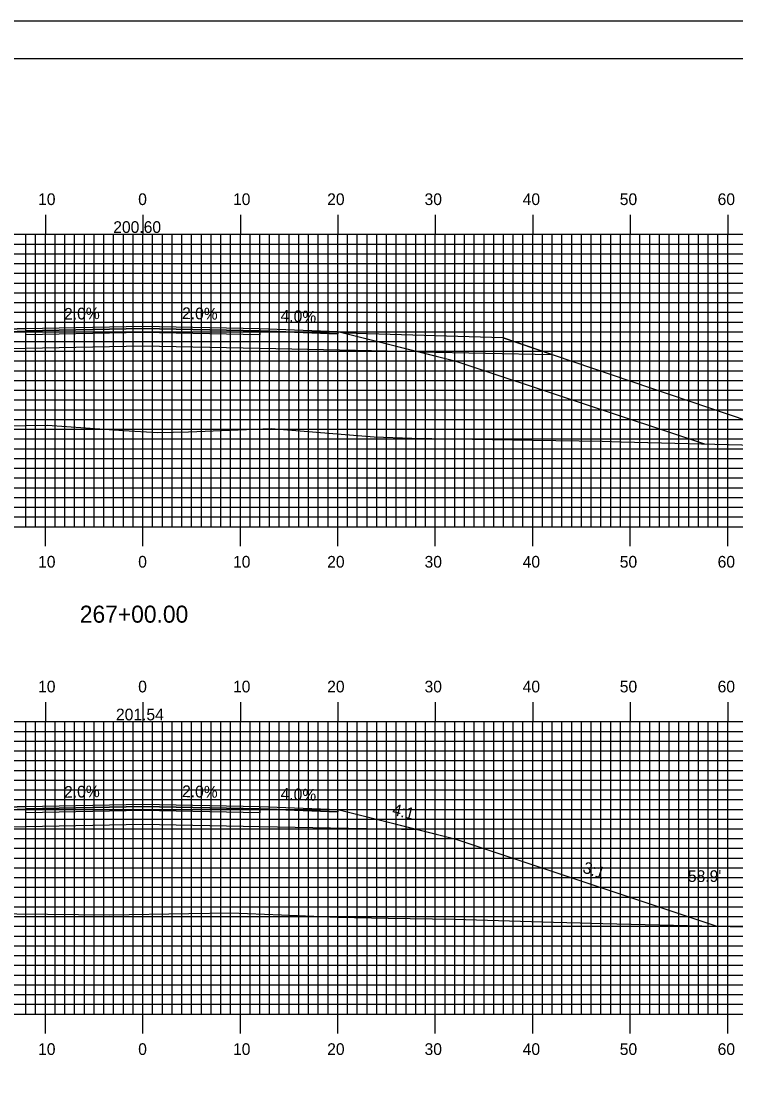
# Model space of a CAD drawing. Extents: x 1807438 to 1807782, y 442591 to 442811.
# Drawn here: x 1807591.8 to 1807665.1, y 442702.5 to 442810.5 of the extents above; entities that cross this region are included whole.
import ezdxf

# ---------------------------------------------------------------- set-up
doc = ezdxf.new("R2010")
doc.units = 0
for name, color, linetype in [('ANNOTATION', 7, 'Continuous'), ('BORDER', 7, 'Continuous'), ('D_Roadway_Centerline', 7, 'Continuous'), ('D_Roadway_Centerline_Text', 7, 'Continuous'), ('D_Roadway_Edge_Shoulder', 7, 'Continuous'), ('D_Roadway_Edge_TW', 7, 'Continuous'), ('D_Roadway_Pavement', 7, 'Continuous'), ('D_Roadway_SlopeLines', 7, 'Continuous'), ('D_Roadway_SubGrade', 7, 'Continuous'), ('D_Text_Standard', 7, 'Continuous'), ('H_V ANNOTATION', 7, 'Continuous'), ('MAJOR', 7, 'Continuous'), ('MINOR', 7, 'Continuous'), ('PLOT BOUNDARY', 7, 'Continuous'), ('S_Roadway_Centerline', 7, 'Continuous')]:
    doc.layers.add(name, color=color, linetype=linetype)

msp = doc.modelspace()

# ---------------------------------------------------------------- linework, layer by layer
at = {"layer": 'BORDER'}
msp.add_lwpolyline([(1807454.67, 442596.67), (1807774.67, 442596.67), (1807774.67, 442806.67), (1807454.67, 442806.67)], close=True, dxfattribs=at)
at = {"layer": 'D_Roadway_Centerline'}
for points in [[(1807554.39, 442769.74), (1807572.27, 442775.7), (1807575.91, 442776.61), (1807584.27, 442778.7), (1807592.27, 442779.02), (1807604.27, 442779.26), (1807616.27, 442779.02), (1807624.27, 442778.7), (1807632.63, 442776.61), (1807636.27, 442775.7), (1807661.88, 442767.17)], [(1807552.34, 442720), (1807572.27, 442726.65), (1807575.91, 442727.56), (1807584.27, 442729.65), (1807592.27, 442729.97), (1807604.27, 442730.21), (1807616.27, 442729.97), (1807624.27, 442729.65), (1807632.63, 442727.56), (1807636.27, 442726.65), (1807663.15, 442717.69)]]:
    msp.add_lwpolyline(points, dxfattribs=at)
at = {"layer": 'D_Roadway_Edge_Shoulder'}
for points in [[(1807592.27, 442779.02), (1807584.27, 442778.7), (1807584.27, 442778.45), (1807592.27, 442778.77)], [(1807616.27, 442779.02), (1807624.27, 442778.7), (1807624.27, 442778.45), (1807616.27, 442778.77)], [(1807592.27, 442729.97), (1807584.27, 442729.65), (1807584.27, 442729.4), (1807592.27, 442729.72)], [(1807616.27, 442729.97), (1807624.27, 442729.65), (1807624.27, 442729.4), (1807616.27, 442729.72)]]:
    msp.add_lwpolyline(points, close=True, dxfattribs=at)
at = {"layer": 'D_Roadway_Edge_TW'}
for points in [[(1807592.27, 442778.77), (1807592.27, 442779.02), (1807604.27, 442779.26), (1807616.27, 442779.02), (1807616.27, 442778.77), (1807604.27, 442779.01)], [(1807592.27, 442729.72), (1807592.27, 442729.97), (1807604.27, 442730.21), (1807616.27, 442729.97), (1807616.27, 442729.72), (1807604.27, 442729.96)]]:
    msp.add_lwpolyline(points, close=True, dxfattribs=at)
at = {"layer": 'D_Roadway_Pavement'}
for points in [[(1807592.27, 442778.36), (1807592.27, 442778.77), (1807604.27, 442779.01), (1807616.27, 442778.77), (1807616.27, 442778.36), (1807604.27, 442778.6)], [(1807592.27, 442729.3), (1807592.27, 442729.72), (1807604.27, 442729.96), (1807616.27, 442729.72), (1807616.27, 442729.3), (1807604.27, 442729.54)]]:
    msp.add_lwpolyline(points, close=True, dxfattribs=at)
at = {"layer": 'D_Roadway_SlopeLines'}
for points in [[(1807624.27, 442778.7), (1807636.27, 442775.7), (1807661.88, 442767.17)], [(1807632.63, 442776.61), (1807646.24, 442776.34), (1807641.22, 442778.04), (1807624.98, 442778.52)], [(1807641.22, 442778.04), (1807644.46, 442776.94), (1807674.31, 442766.84)], [(1807624.27, 442729.65), (1807636.27, 442726.65), (1807663.15, 442717.69)]]:
    msp.add_lwpolyline(points, dxfattribs=at)
at = {"layer": 'D_Roadway_SubGrade'}
for points in [[(1807592.27, 442776.94), (1807575.91, 442776.61), (1807584.27, 442778.7), (1807584.27, 442778.45), (1807592.27, 442778.77), (1807604.27, 442779.01), (1807616.27, 442778.77), (1807624.27, 442778.45), (1807624.27, 442778.7), (1807632.63, 442776.61), (1807616.27, 442776.94), (1807604.27, 442777.18)], [(1807592.27, 442727.88), (1807575.91, 442727.56), (1807584.27, 442729.65), (1807584.27, 442729.4), (1807592.27, 442729.72), (1807604.27, 442729.96), (1807616.27, 442729.72), (1807624.27, 442729.4), (1807624.27, 442729.65), (1807632.63, 442727.56), (1807616.27, 442727.88), (1807604.27, 442728.12)]]:
    msp.add_lwpolyline(points, close=True, dxfattribs=at)
at = {"layer": 'MAJOR'}
for p, q in [((1807594.27, 442790.67), (1807594.27, 442788.67)), ((1807604.27, 442790.67), (1807604.27, 442788.67)), ((1807614.27, 442790.67), (1807614.27, 442788.67)), ((1807624.27, 442790.67), (1807624.27, 442788.67)), ((1807634.27, 442790.67), (1807634.27, 442788.67)), ((1807644.27, 442790.67), (1807644.27, 442788.67)), ((1807654.27, 442790.67), (1807654.27, 442788.67)), ((1807664.27, 442790.67), (1807664.27, 442788.67)), ((1807464.27, 442788.67), (1807744.27, 442788.67)), ((1807464.27, 442788.67), (1807744.27, 442788.67)), ((1807594.27, 442758.67), (1807594.27, 442788.67)), ((1807604.27, 442758.67), (1807604.27, 442788.67)), ((1807614.27, 442758.67), (1807614.27, 442788.67)), ((1807624.27, 442758.67), (1807624.27, 442788.67)), ((1807634.27, 442758.67), (1807634.27, 442788.67)), ((1807644.27, 442758.67), (1807644.27, 442788.67)), ((1807654.27, 442758.67), (1807654.27, 442788.67)), ((1807664.27, 442758.67), (1807664.27, 442788.67)), ((1807464.27, 442783.67), (1807744.27, 442783.67)), ((1807464.27, 442778.67), (1807744.27, 442778.67)), ((1807464.27, 442773.67), (1807744.27, 442773.67)), ((1807464.27, 442768.67), (1807744.27, 442768.67)), ((1807464.27, 442763.67), (1807744.27, 442763.67)), ((1807464.27, 442758.67), (1807744.27, 442758.67)), ((1807464.27, 442758.67), (1807744.27, 442758.67)), ((1807594.27, 442756.66), (1807594.27, 442758.67)), ((1807604.27, 442756.66), (1807604.27, 442758.67)), ((1807614.27, 442756.66), (1807614.27, 442758.67)), ((1807624.27, 442756.66), (1807624.27, 442758.67)), ((1807634.27, 442756.66), (1807634.27, 442758.67)), ((1807644.27, 442756.66), (1807644.27, 442758.67)), ((1807654.27, 442756.66), (1807654.27, 442758.67)), ((1807664.27, 442756.66), (1807664.27, 442758.67)), ((1807594.27, 442740.67), (1807594.27, 442738.67)), ((1807604.27, 442740.67), (1807604.27, 442738.67)), ((1807614.27, 442740.67), (1807614.27, 442738.67)), ((1807624.27, 442740.67), (1807624.27, 442738.67)), ((1807634.27, 442740.67), (1807634.27, 442738.67)), ((1807644.27, 442740.67), (1807644.27, 442738.67)), ((1807654.27, 442740.67), (1807654.27, 442738.67)), ((1807664.27, 442740.67), (1807664.27, 442738.67)), ((1807464.27, 442738.67), (1807744.27, 442738.67)), ((1807464.27, 442738.67), (1807744.27, 442738.67)), ((1807594.27, 442708.67), (1807594.27, 442738.67)), ((1807604.27, 442708.67), (1807604.27, 442738.67)), ((1807614.27, 442708.67), (1807614.27, 442738.67)), ((1807624.27, 442708.67), (1807624.27, 442738.67)), ((1807634.27, 442708.67), (1807634.27, 442738.67)), ((1807644.27, 442708.67), (1807644.27, 442738.67)), ((1807654.27, 442708.67), (1807654.27, 442738.67)), ((1807664.27, 442708.67), (1807664.27, 442738.67)), ((1807464.27, 442733.67), (1807744.27, 442733.67)), ((1807464.27, 442728.67), (1807744.27, 442728.67)), ((1807464.27, 442723.67), (1807744.27, 442723.67)), ((1807464.27, 442718.67), (1807744.27, 442718.67)), ((1807464.27, 442713.67), (1807744.27, 442713.67)), ((1807464.27, 442708.67), (1807744.27, 442708.67)), ((1807464.27, 442708.67), (1807744.27, 442708.67)), ((1807594.27, 442706.66), (1807594.27, 442708.67)), ((1807604.27, 442706.66), (1807604.27, 442708.67)), ((1807614.27, 442706.66), (1807614.27, 442708.67)), ((1807624.27, 442706.66), (1807624.27, 442708.67)), ((1807634.27, 442706.66), (1807634.27, 442708.67)), ((1807644.27, 442706.66), (1807644.27, 442708.67)), ((1807654.27, 442706.66), (1807654.27, 442708.67)), ((1807664.27, 442706.66), (1807664.27, 442708.67))]:
    msp.add_line(p, q, dxfattribs=at)
at = {"layer": 'MINOR'}
for p, q in [((1807592.27, 442758.67), (1807592.27, 442788.67)), ((1807593.27, 442758.67), (1807593.27, 442788.67)), ((1807595.27, 442758.67), (1807595.27, 442788.67)), ((1807596.27, 442758.67), (1807596.27, 442788.67)), ((1807597.27, 442758.67), (1807597.27, 442788.67)), ((1807598.27, 442758.67), (1807598.27, 442788.67)), ((1807599.27, 442758.67), (1807599.27, 442788.67)), ((1807600.27, 442758.67), (1807600.27, 442788.67)), ((1807601.27, 442758.67), (1807601.27, 442788.67)), ((1807602.27, 442758.67), (1807602.27, 442788.67)), ((1807603.27, 442758.67), (1807603.27, 442788.67)), ((1807605.27, 442758.67), (1807605.27, 442788.67)), ((1807606.27, 442758.67), (1807606.27, 442788.67)), ((1807607.27, 442758.67), (1807607.27, 442788.67)), ((1807608.27, 442758.67), (1807608.27, 442788.67)), ((1807609.27, 442758.67), (1807609.27, 442788.67)), ((1807610.27, 442758.67), (1807610.27, 442788.67)), ((1807611.27, 442758.67), (1807611.27, 442788.67)), ((1807612.27, 442758.67), (1807612.27, 442788.67)), ((1807613.27, 442758.67), (1807613.27, 442788.67)), ((1807615.27, 442758.67), (1807615.27, 442788.67)), ((1807616.27, 442758.67), (1807616.27, 442788.67)), ((1807617.27, 442758.67), (1807617.27, 442788.67)), ((1807618.27, 442758.67), (1807618.27, 442788.67)), ((1807619.27, 442758.67), (1807619.27, 442788.67)), ((1807620.27, 442758.67), (1807620.27, 442788.67)), ((1807621.27, 442758.67), (1807621.27, 442788.67)), ((1807622.27, 442758.67), (1807622.27, 442788.67)), ((1807623.27, 442758.67), (1807623.27, 442788.67)), ((1807625.27, 442758.67), (1807625.27, 442788.67)), ((1807626.27, 442758.67), (1807626.27, 442788.67)), ((1807627.27, 442758.67), (1807627.27, 442788.67)), ((1807628.27, 442758.67), (1807628.27, 442788.67)), ((1807629.27, 442758.67), (1807629.27, 442788.67)), ((1807630.27, 442758.67), (1807630.27, 442788.67)), ((1807631.27, 442758.67), (1807631.27, 442788.67)), ((1807632.27, 442758.67), (1807632.27, 442788.67)), ((1807633.27, 442758.67), (1807633.27, 442788.67)), ((1807635.27, 442758.67), (1807635.27, 442788.67)), ((1807636.27, 442758.67), (1807636.27, 442788.67)), ((1807637.27, 442758.67), (1807637.27, 442788.67)), ((1807638.27, 442758.67), (1807638.27, 442788.67)), ((1807639.27, 442758.67), (1807639.27, 442788.67)), ((1807640.27, 442758.67), (1807640.27, 442788.67)), ((1807641.27, 442758.67), (1807641.27, 442788.67)), ((1807642.27, 442758.67), (1807642.27, 442788.67)), ((1807643.27, 442758.67), (1807643.27, 442788.67)), ((1807645.27, 442758.67), (1807645.27, 442788.67)), ((1807646.27, 442758.67), (1807646.27, 442788.67)), ((1807647.27, 442758.67), (1807647.27, 442788.67)), ((1807648.27, 442758.67), (1807648.27, 442788.67)), ((1807649.27, 442758.67), (1807649.27, 442788.67)), ((1807650.27, 442758.67), (1807650.27, 442788.67)), ((1807651.27, 442758.67), (1807651.27, 442788.67)), ((1807652.27, 442758.67), (1807652.27, 442788.67)), ((1807653.27, 442758.67), (1807653.27, 442788.67)), ((1807655.27, 442758.67), (1807655.27, 442788.67)), ((1807656.27, 442758.67), (1807656.27, 442788.67)), ((1807657.27, 442758.67), (1807657.27, 442788.67)), ((1807658.27, 442758.67), (1807658.27, 442788.67)), ((1807659.27, 442758.67), (1807659.27, 442788.67)), ((1807660.27, 442758.67), (1807660.27, 442788.67)), ((1807661.27, 442758.67), (1807661.27, 442788.67)), ((1807662.27, 442758.67), (1807662.27, 442788.67)), ((1807663.27, 442758.67), (1807663.27, 442788.67)), ((1807464.27, 442787.67), (1807744.27, 442787.67)), ((1807464.27, 442786.67), (1807744.27, 442786.67)), ((1807464.27, 442785.67), (1807744.27, 442785.67)), ((1807464.27, 442784.67), (1807744.27, 442784.67)), ((1807464.27, 442782.67), (1807744.27, 442782.67)), ((1807464.27, 442781.67), (1807744.27, 442781.67)), ((1807464.27, 442780.67), (1807744.27, 442780.67)), ((1807464.27, 442779.67), (1807744.27, 442779.67)), ((1807464.27, 442777.67), (1807744.27, 442777.67)), ((1807464.27, 442776.67), (1807744.27, 442776.67)), ((1807464.27, 442775.67), (1807744.27, 442775.67)), ((1807464.27, 442774.67), (1807744.27, 442774.67)), ((1807464.27, 442772.67), (1807744.27, 442772.67)), ((1807464.27, 442771.67), (1807744.27, 442771.67)), ((1807464.27, 442770.67), (1807744.27, 442770.67)), ((1807464.27, 442769.67), (1807744.27, 442769.67)), ((1807464.27, 442767.67), (1807744.27, 442767.67)), ((1807464.27, 442766.67), (1807744.27, 442766.67)), ((1807464.27, 442765.67), (1807744.27, 442765.67)), ((1807464.27, 442764.67), (1807744.27, 442764.67)), ((1807464.27, 442762.67), (1807744.27, 442762.67)), ((1807464.27, 442761.67), (1807744.27, 442761.67)), ((1807464.27, 442760.67), (1807744.27, 442760.67)), ((1807464.27, 442759.67), (1807744.27, 442759.67)), ((1807592.27, 442708.67), (1807592.27, 442738.67)), ((1807593.27, 442708.67), (1807593.27, 442738.67)), ((1807595.27, 442708.67), (1807595.27, 442738.67)), ((1807596.27, 442708.67), (1807596.27, 442738.67)), ((1807597.27, 442708.67), (1807597.27, 442738.67)), ((1807598.27, 442708.67), (1807598.27, 442738.67)), ((1807599.27, 442708.67), (1807599.27, 442738.67)), ((1807600.27, 442708.67), (1807600.27, 442738.67)), ((1807601.27, 442708.67), (1807601.27, 442738.67)), ((1807602.27, 442708.67), (1807602.27, 442738.67)), ((1807603.27, 442708.67), (1807603.27, 442738.67)), ((1807605.27, 442708.67), (1807605.27, 442738.67)), ((1807606.27, 442708.67), (1807606.27, 442738.67)), ((1807607.27, 442708.67), (1807607.27, 442738.67)), ((1807608.27, 442708.67), (1807608.27, 442738.67)), ((1807609.27, 442708.67), (1807609.27, 442738.67)), ((1807610.27, 442708.67), (1807610.27, 442738.67)), ((1807611.27, 442708.67), (1807611.27, 442738.67)), ((1807612.27, 442708.67), (1807612.27, 442738.67)), ((1807613.27, 442708.67), (1807613.27, 442738.67)), ((1807615.27, 442708.67), (1807615.27, 442738.67)), ((1807616.27, 442708.67), (1807616.27, 442738.67)), ((1807617.27, 442708.67), (1807617.27, 442738.67)), ((1807618.27, 442708.67), (1807618.27, 442738.67)), ((1807619.27, 442708.67), (1807619.27, 442738.67)), ((1807620.27, 442708.67), (1807620.27, 442738.67)), ((1807621.27, 442708.67), (1807621.27, 442738.67)), ((1807622.27, 442708.67), (1807622.27, 442738.67)), ((1807623.27, 442708.67), (1807623.27, 442738.67)), ((1807625.27, 442708.67), (1807625.27, 442738.67)), ((1807626.27, 442708.67), (1807626.27, 442738.67)), ((1807627.27, 442708.67), (1807627.27, 442738.67)), ((1807628.27, 442708.67), (1807628.27, 442738.67)), ((1807629.27, 442708.67), (1807629.27, 442738.67)), ((1807630.27, 442708.67), (1807630.27, 442738.67)), ((1807631.27, 442708.67), (1807631.27, 442738.67)), ((1807632.27, 442708.67), (1807632.27, 442738.67)), ((1807633.27, 442708.67), (1807633.27, 442738.67)), ((1807635.27, 442708.67), (1807635.27, 442738.67)), ((1807636.27, 442708.67), (1807636.27, 442738.67)), ((1807637.27, 442708.67), (1807637.27, 442738.67)), ((1807638.27, 442708.67), (1807638.27, 442738.67)), ((1807639.27, 442708.67), (1807639.27, 442738.67)), ((1807640.27, 442708.67), (1807640.27, 442738.67)), ((1807641.27, 442708.67), (1807641.27, 442738.67)), ((1807642.27, 442708.67), (1807642.27, 442738.67)), ((1807643.27, 442708.67), (1807643.27, 442738.67)), ((1807645.27, 442708.67), (1807645.27, 442738.67)), ((1807646.27, 442708.67), (1807646.27, 442738.67)), ((1807647.27, 442708.67), (1807647.27, 442738.67)), ((1807648.27, 442708.67), (1807648.27, 442738.67)), ((1807649.27, 442708.67), (1807649.27, 442738.67)), ((1807650.27, 442708.67), (1807650.27, 442738.67)), ((1807651.27, 442708.67), (1807651.27, 442738.67)), ((1807652.27, 442708.67), (1807652.27, 442738.67)), ((1807653.27, 442708.67), (1807653.27, 442738.67)), ((1807655.27, 442708.67), (1807655.27, 442738.67)), ((1807656.27, 442708.67), (1807656.27, 442738.67)), ((1807657.27, 442708.67), (1807657.27, 442738.67)), ((1807658.27, 442708.67), (1807658.27, 442738.67)), ((1807659.27, 442708.67), (1807659.27, 442738.67)), ((1807660.27, 442708.67), (1807660.27, 442738.67)), ((1807661.27, 442708.67), (1807661.27, 442738.67)), ((1807662.27, 442708.67), (1807662.27, 442738.67)), ((1807663.27, 442708.67), (1807663.27, 442738.67)), ((1807464.27, 442737.67), (1807744.27, 442737.67)), ((1807464.27, 442736.67), (1807744.27, 442736.67)), ((1807464.27, 442735.67), (1807744.27, 442735.67)), ((1807464.27, 442734.67), (1807744.27, 442734.67)), ((1807464.27, 442732.67), (1807744.27, 442732.67)), ((1807464.27, 442731.67), (1807744.27, 442731.67)), ((1807464.27, 442730.67), (1807744.27, 442730.67)), ((1807464.27, 442729.67), (1807744.27, 442729.67)), ((1807464.27, 442727.67), (1807744.27, 442727.67)), ((1807464.27, 442726.67), (1807744.27, 442726.67)), ((1807464.27, 442725.67), (1807744.27, 442725.67)), ((1807464.27, 442724.67), (1807744.27, 442724.67)), ((1807464.27, 442722.67), (1807744.27, 442722.67)), ((1807464.27, 442721.67), (1807744.27, 442721.67)), ((1807464.27, 442720.67), (1807744.27, 442720.67)), ((1807464.27, 442719.67), (1807744.27, 442719.67)), ((1807464.27, 442717.67), (1807744.27, 442717.67)), ((1807464.27, 442716.67), (1807744.27, 442716.67)), ((1807464.27, 442715.67), (1807744.27, 442715.67)), ((1807464.27, 442714.67), (1807744.27, 442714.67)), ((1807464.27, 442712.67), (1807744.27, 442712.67)), ((1807464.27, 442711.67), (1807744.27, 442711.67)), ((1807464.27, 442710.67), (1807744.27, 442710.67)), ((1807464.27, 442709.67), (1807744.27, 442709.67))]:
    msp.add_line(p, q, dxfattribs=at)
at = {"layer": 'PLOT BOUNDARY'}
msp.add_lwpolyline([(1807438.49, 442590.55), (1807778.49, 442590.55), (1807778.49, 442810.55), (1807438.49, 442810.55)], close=True, dxfattribs=at)
at = {"layer": 'S_Roadway_Centerline'}
for points in [[(1807536.03, 442770.16), (1807544.98, 442769.98), (1807550.6, 442769.85), (1807559.37, 442769.61), (1807566.7, 442769.37), (1807577.74, 442769.05), (1807582.52, 442769), (1807587.66, 442769), (1807594.5, 442769.07), (1807602.27, 442768.53), (1807605.8, 442768.34), (1807608.96, 442768.4), (1807617.43, 442768.75), (1807628, 442767.9), (1807631.85, 442767.74), (1807644.28, 442767.53), (1807651.38, 442767.45), (1807653.36, 442767.39), (1807673.96, 442766.85)], [(1807542.68, 442720.33), (1807543.32, 442720.35), (1807552.61, 442719.99), (1807565.72, 442719.56), (1807566.72, 442719.52), (1807568, 442719.53), (1807578.3, 442719.65), (1807591.34, 442718.95), (1807600.81, 442718.83), (1807608.98, 442718.98), (1807613.27, 442719.04), (1807618.49, 442718.84), (1807624.28, 442718.61), (1807629.43, 442718.5), (1807636.24, 442718.41), (1807646.41, 442718.09), (1807649.13, 442718.02), (1807651.47, 442717.95), (1807668.87, 442717.56)]]:
    msp.add_lwpolyline(points, dxfattribs=at)

# ---------------------------------------------------------------- texts
at = {"layer": 'ANNOTATION'}
for s, rotation, p in [('2.0%', 1.1458, (1807596.2, 442779.9)), ('2.0%', 358.8542, (1807608.28, 442779.98)), ('4.0%', 357.7094, (1807618.38, 442779.74)), ('2.0%', 1.1458, (1807596.2, 442730.85)), ('2.0%', 358.8542, (1807608.28, 442730.93)), ('4.0%', 357.7094, (1807618.38, 442730.68)), ('4:1', 345.9638, (1807629.78, 442729.13)), ('3:1', 341.5652, (1807649.31, 442723.21))]:
    msp.add_text(s, height=1.2, rotation=rotation, dxfattribs=at).set_placement(p)
at = {"layer": 'D_Roadway_Centerline'}
for s, p in [('C', (1807604.27, 442779.26)), ('L', (1807604.27, 442779.26)), ('C', (1807604.27, 442730.21)), ('L', (1807604.27, 442730.2))]:
    msp.add_text(s, height=0.0146, dxfattribs=at).set_placement(p)
at = {"layer": 'D_Roadway_Centerline_Text'}
for s, p in [('200.60', (1807601.23, 442788.81)), ('201.54', (1807601.51, 442738.8))]:
    msp.add_text(s, height=1.2, dxfattribs=at).set_placement(p)
at = {"layer": 'D_Text_Standard'}
msp.add_text("58.9'", height=1.2, dxfattribs=at).set_placement((1807660.19, 442722.22))
at = {"layer": 'H_V ANNOTATION'}
for s, height, p in [('10', 1.2, (1807593.52, 442791.67)), ('0', 1.2, (1807603.79, 442791.67)), ('10', 1.2, (1807613.52, 442791.67)), ('20', 1.2, (1807623.18, 442791.67)), ('30', 1.2, (1807633.17, 442791.67)), ('40', 1.2, (1807643.24, 442791.67)), ('50', 1.2, (1807653.2, 442791.67)), ('60', 1.2, (1807663.24, 442791.67)), ('10', 1.2, (1807593.52, 442754.47)), ('0', 1.2, (1807603.79, 442754.47)), ('10', 1.2, (1807613.52, 442754.47)), ('20', 1.2, (1807623.18, 442754.47)), ('30', 1.2, (1807633.17, 442754.47)), ('40', 1.2, (1807643.24, 442754.47)), ('50', 1.2, (1807653.2, 442754.47)), ('60', 1.2, (1807663.24, 442754.47)), ('267+00.00', 1.75, (1807597.8, 442748.82)), ('10', 1.2, (1807593.52, 442741.67)), ('0', 1.2, (1807603.79, 442741.67)), ('10', 1.2, (1807613.52, 442741.67)), ('20', 1.2, (1807623.18, 442741.67)), ('30', 1.2, (1807633.17, 442741.67)), ('40', 1.2, (1807643.24, 442741.67)), ('50', 1.2, (1807653.2, 442741.67)), ('60', 1.2, (1807663.24, 442741.67)), ('10', 1.2, (1807593.52, 442704.47)), ('0', 1.2, (1807603.79, 442704.47)), ('10', 1.2, (1807613.52, 442704.47)), ('20', 1.2, (1807623.18, 442704.47)), ('30', 1.2, (1807633.17, 442704.47)), ('40', 1.2, (1807643.24, 442704.47)), ('50', 1.2, (1807653.2, 442704.47)), ('60', 1.2, (1807663.24, 442704.47))]:
    msp.add_text(s, height=height, dxfattribs=at).set_placement(p)

doc.saveas('drawing.dxf')
